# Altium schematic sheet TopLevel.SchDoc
size A; SheetNumber: 1; SheetTotal: 6
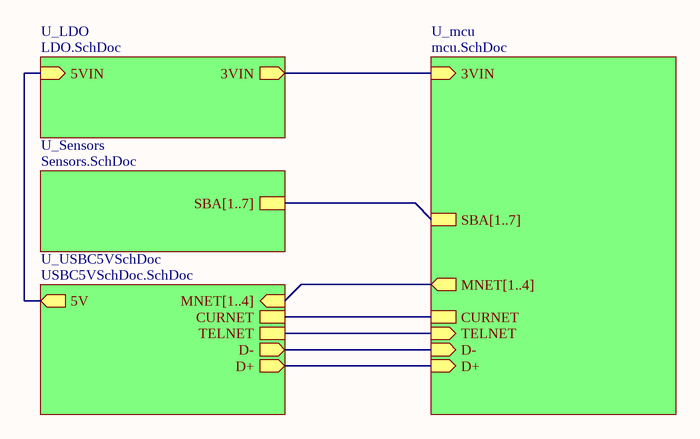
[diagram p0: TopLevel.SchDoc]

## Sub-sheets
U_LDO = LDO.SchDoc: 3VIN (out), 5VIN (in)
U_mcu = mcu.SchDoc: D- (in), D+ (in), TELNET (in), CURNET, 3VIN (in), SBA[1..7], MNET[1..4] (out)
U_Sensors = Sensors.SchDoc: SBA[1..7]
U_USBC5VSchDoc = USBC5VSchDoc.SchDoc: 5V (out), D+ (out), D- (out), MNET[1..4] (in), CURNET, TELNET

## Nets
(unnamed): sheet U_mcu/D-, sheet U_USBC5VSchDoc/D-
(unnamed): sheet U_mcu/D+, sheet U_USBC5VSchDoc/D+  [a separate net that carries the same name]
(unnamed): sheet U_mcu/TELNET, sheet U_USBC5VSchDoc/TELNET  [a separate net that carries the same name]
(unnamed): sheet U_mcu/CURNET, sheet U_USBC5VSchDoc/CURNET  [a separate net that carries the same name]
(unnamed): sheet U_mcu/3VIN, sheet U_LDO/3VIN  [a separate net that carries the same name]
(unnamed): sheet U_LDO/5VIN, sheet U_USBC5VSchDoc/5V  [a separate net that carries the same name]

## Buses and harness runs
bus sheet U_mcu/MNET[1..4] = sheet U_USBC5VSchDoc/MNET[1..4]
bus sheet U_mcu/SBA[1..7] = sheet U_Sensors/SBA[1..7]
